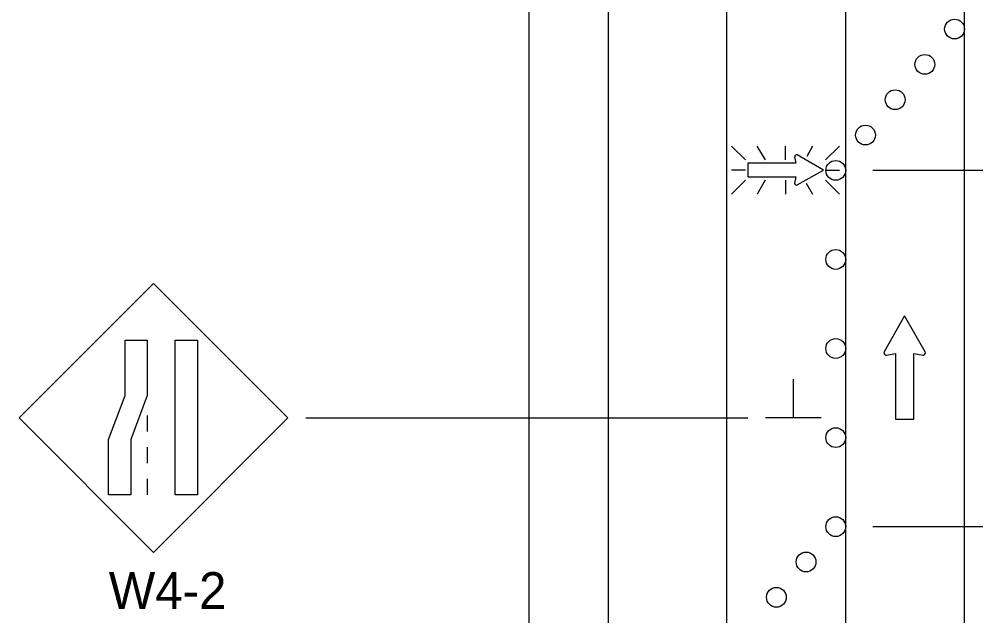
# Model space of a CAD drawing. Extents: x 16724 to 18475, y 7025 to 8210.
# Drawn here: x 16765.3 to 16958.6, y 7881.5 to 8002 of the extents above; entities that cross this region are included whole.
import ezdxf

# ---------------------------------------------------------------- set-up
doc = ezdxf.new("R2010")
doc.units = 0
for name, color, linetype in [('MT_SCRATCH_LEVEL_E', 7, 'Continuous'), ('PAVT_EDGE_EX', 7, 'Continuous'), ('TRAFFIC_SIGNS_PR', 7, 'Continuous'), ('TYPICAL_TEXT_DIMEN_PR', 7, 'Continuous')]:
    doc.layers.add(name, color=color, linetype=linetype)

msp = doc.modelspace()

# ---------------------------------------------------------------- linework, layer by layer
at = {"layer": 'MT_SCRATCH_LEVEL_E'}
for p, q in [((16944.2, 7942.06), (16940.09, 7934.82)), ((16948.34, 7934.82), (16944.2, 7942.06)), ((16940.57, 7934.13), (16942.35, 7934.45)), ((16942.35, 7934.45), (16942.35, 7921.19)), ((16946.09, 7921.19), (16946.09, 7934.45)), ((16946.09, 7934.45), (16947.87, 7934.13)), ((16942.35, 7921.19), (16946.09, 7921.19))]:
    msp.add_line(p, q, dxfattribs=at)
for centre, start, end in [((16940.49, 7934.59), 150.4248, 279.9638), ((16947.93, 7934.59), 260.0362, 29.7731)]:
    msp.add_arc(centre, 0.463, start, end, dxfattribs=at)
at = {"layer": 'PAVT_EDGE_EX'}
for p, q in [((16868.3, 8210.42), (16868.3, 7546.41)), ((16884.3, 8210.42), (16884.3, 7546.41)), ((16908.3, 7546.41), (16908.3, 8134.51)), ((16932.3, 7546.41), (16932.3, 8134.51)), ((16956.3, 7546.41), (16956.3, 8134.51))]:
    msp.add_line(p, q, dxfattribs=at)
for points in [[(16908.3, 7946.41), (16908.3, 7971.41)], [(16932.3, 7946.41), (16932.3, 7971.41)], [(16956.3, 7946.41), (16956.3, 7971.41)]]:
    msp.add_lwpolyline(points, dxfattribs=at)
at = {"layer": 'TRAFFIC_SIGNS_PR'}
for p, q in [((16912.07, 7973.58), (16909.25, 7976.4)), ((16914.37, 7976.4), (16915.99, 7973.58)), ((16920.15, 7973.58), (16920.15, 7976.4)), ((16925.62, 7976.4), (16924.42, 7974.31)), ((16931.06, 7976.4), (16928.24, 7973.58)), ((16912.07, 7971.55), (16909.25, 7971.55)), ((16928.24, 7971.55), (16931.06, 7971.55)), ((16912.07, 7969.52), (16909.25, 7966.7)), ((16916.02, 7969.52), (16914.39, 7966.7)), ((16920.15, 7969.52), (16920.15, 7966.7)), ((16924.34, 7968.88), (16925.6, 7966.7)), ((16931.06, 7966.7), (16928.24, 7969.52)), ((16792.43, 7948.59), (16765.28, 7921.44)), ((16819.58, 7921.44), (16792.43, 7948.59)), ((16765.28, 7921.44), (16792.43, 7894.29)), ((16791.18, 7921.93), (16791.18, 7918.73)), ((16792.43, 7894.29), (16819.58, 7921.44)), ((16791.18, 7915.53), (16791.18, 7912.33)), ((16791.18, 7909.13), (16791.18, 7905.93))]:
    msp.add_line(p, q, dxfattribs=at)
for points in [[(16922.48, 7968.54), (16927.79, 7971.55), (16922.48, 7974.59)], [(16921.98, 7974.23), (16922.21, 7972.94), (16912.49, 7972.94), (16912.49, 7970.19), (16922.21, 7970.19), (16921.98, 7968.89)]]:
    msp.add_lwpolyline(points, dxfattribs=at)
for points in [[(16791.18, 7937.18), (16791.18, 7926), (16787.84, 7917.11), (16787.84, 7905.93), (16783.34, 7905.93), (16783.34, 7917.11), (16786.69, 7926), (16786.69, 7937.18)], [(16801.32, 7937.18), (16801.32, 7905.93), (16796.83, 7905.93), (16796.83, 7937.18)]]:
    msp.add_lwpolyline(points, close=True, dxfattribs=at)
for centre in [(16954.29, 8000.04), (16954.29, 8000.04), (16948.29, 7992.9), (16942.29, 7985.76), (16936.29, 7978.62), (16930.29, 7971.48), (16930.29, 7953.48), (16930.29, 7935.48), (16930.29, 7917.48), (16930.29, 7899.48), (16924.29, 7892.34), (16918.29, 7885.2)]:
    msp.add_circle(centre, 2, dxfattribs=at)
for centre, start, end in [((16922.32, 7974.29), 61.4833, 189.9593), ((16922.32, 7968.83), 170.7308, 298.8916)]:
    msp.add_arc(centre, 0.341, start, end, dxfattribs=at)
at = {"layer": 'TYPICAL_TEXT_DIMEN_PR'}
for p, q in [((17072.34, 7971.48), (16937.79, 7971.48)), ((16921.73, 7921.48), (16921.73, 7929.26)), ((16823.18, 7921.48), (16912.49, 7921.48)), ((16927.36, 7921.48), (16916.11, 7921.48)), ((16937.79, 7899.48), (17072.34, 7899.48))]:
    msp.add_line(p, q, dxfattribs=at)

# ---------------------------------------------------------------- texts
at = {"layer": 'TRAFFIC_SIGNS_PR'}
msp.add_text('W4-2', height=7.44, dxfattribs=at).set_placement((16783.39, 7882.85))

doc.saveas('drawing.dxf')
